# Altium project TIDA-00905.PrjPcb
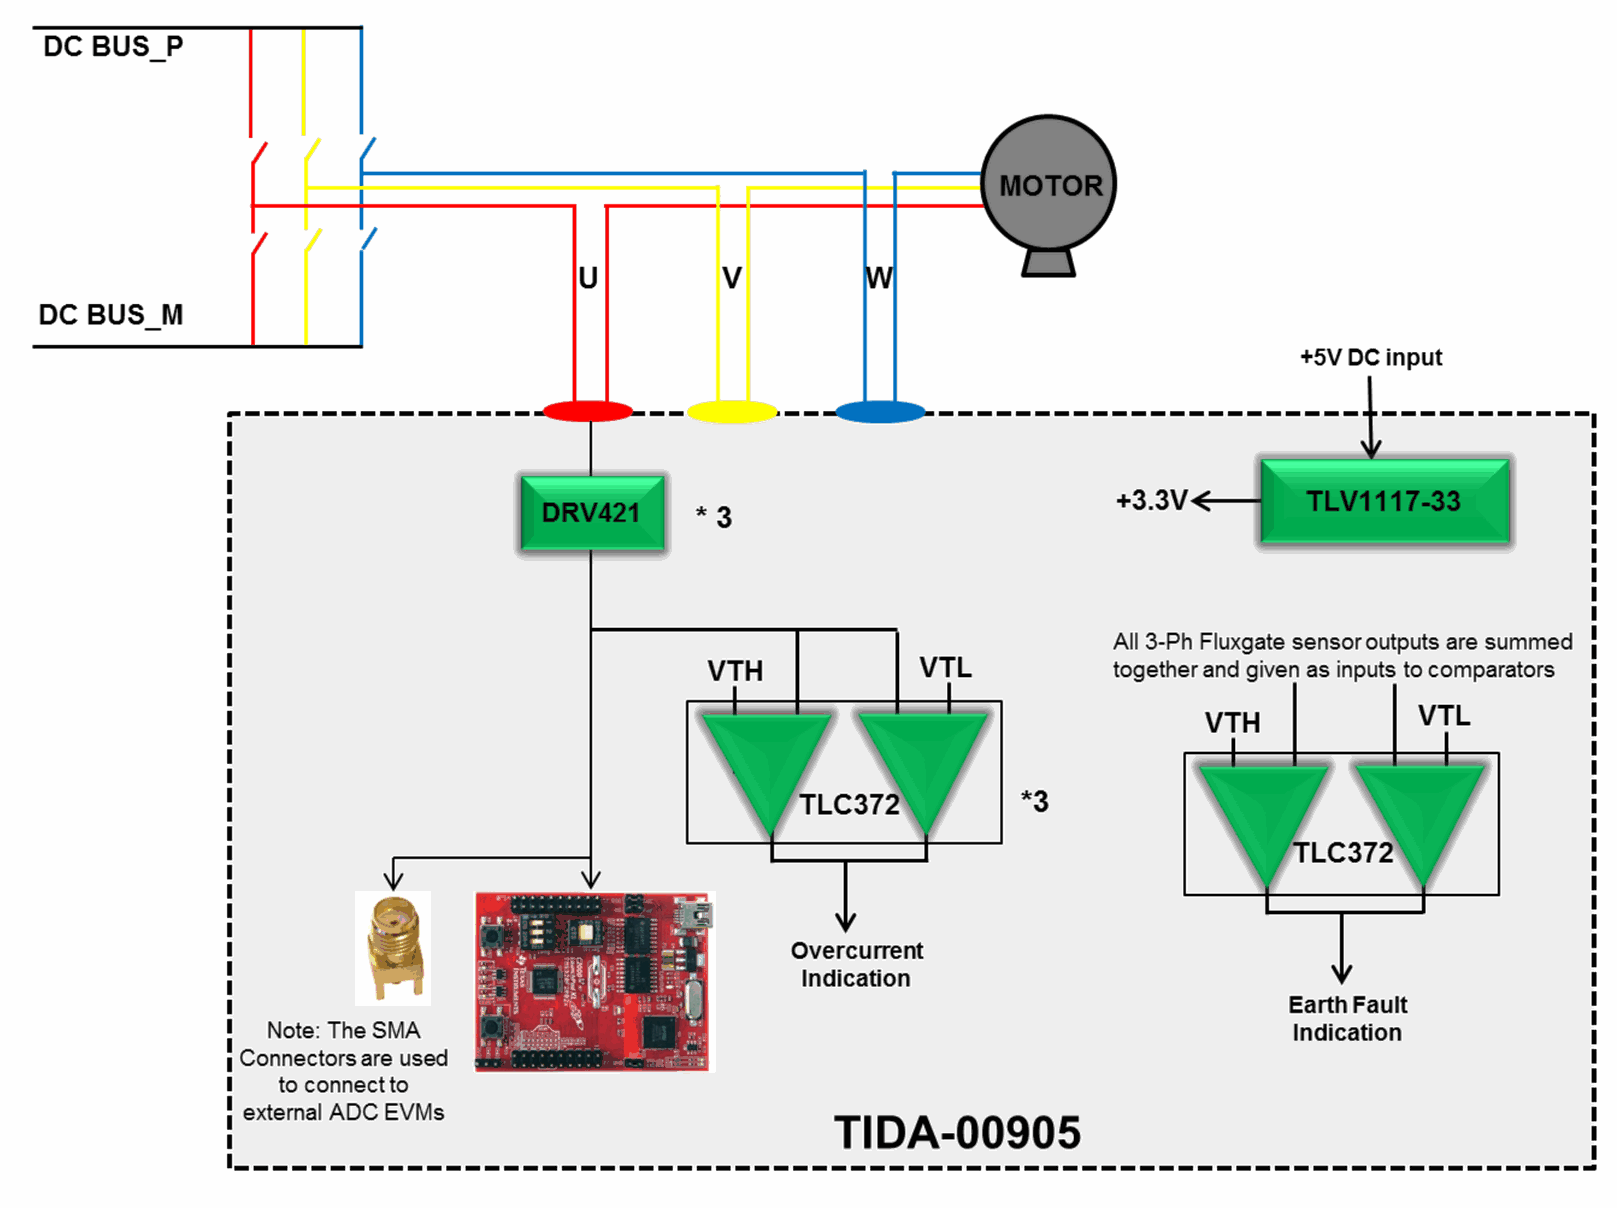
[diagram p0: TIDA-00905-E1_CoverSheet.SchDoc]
CopyrightYear: 2016; PCB_Layout: Avinash N; PCB_Rev: E1; PRJ_Customer: Public Release; PRJ_Engineer: Sanjay Pithadia; PRJ_Number: TIDA-00905; PRJ_Title: 3-Ph Current Sensing using DRV421; SCH_Rev: E1; TechSupport: http://www.ti.com/support; TID: TIDA-00905
6 sheets, 197 parts. Net scope: flat (ports and power ports of the same name join across sheets).
Board file: TIDA-00905-E1.PcbDoc
Sheets:
  TIDA-00905-E1_CoverSheet.SchDoc
  TIDA-00905-E1_P1.SchDoc
  TIDA-00905-E1_P2.SchDoc
  TIDA-00905-E1_P3.SchDoc
  TIDA-00905-E1_P4.SchDoc
  TIDA-00905-E1_Hardware.SchDoc

## Sheet TIDA-00905-E1_CoverSheet.SchDoc: Block Diagram
size 431 x 279 mm; Date: Not shown in title block; ApprovedBy: Not shown in title block; CheckedBy: Not shown in title block; Author: Not shown in title block; CompanyName: Not shown in title block; DrawnBy: Sanjay Pithadia; Engineer: Sanjay Pithadia; Organization: Not shown in title block; Address1: Not shown in title block; Address2: Not shown in title block; Address3: Not shown in title block; Address4: Not shown in title block; DocumentNumber: 1; Revision: Use project parameter SCH_Rev; SheetNumber: 1; SheetTotal: 6; PageSetup: Record=PageOptions¦CenterHorizontal=True¦CenterVertical=True¦PrintScale=1.00¦XCorrection=1.00¦YCorrection=1.00¦PrintKind=0¦BorderSize=5000000¦LeftOffset=0¦BottomOffset=0¦Orientation=2¦PaperLength=1000¦PaperWidth=1000¦Scale=100¦PaperSource=15¦PrintQuality=600¦MediaType=1¦DitherType=10¦PaperKind=Letter¦PrintScaleMode=1

## Sheet TIDA-00905-E1_P1.SchDoc
size 431 x 279 mm; Date: Not shown in title block; ApprovedBy: Not shown in title block; CheckedBy: Not shown in title block; Author: Not shown in title block; CompanyName: Not shown in title block; Engineer: Not shown in title block; Organization: Not shown in title block; Address1: Not shown in title block; Address2: Not shown in title block; Address3: Not shown in title block; Address4: Not shown in title block; DocumentNumber: 1; Revision: Use project parameter SCH_Rev; SheetNumber: 2; SheetTotal: 6; PageSetup: Record=PageOptions¦CenterHorizontal=True¦CenterVertical=True¦PrintScale=1.00¦XCorrection=1.00¦YCorrection=1.00¦PrintKind=0¦BorderSize=5000000¦LeftOffset=0¦BottomOffset=0¦Orientation=2¦PaperLength=1000¦PaperWidth=1000¦Scale=100¦PaperSource=15¦PrintQuality=600¦MediaType=1¦DitherType=10¦PaperKind=Letter¦PrintScaleMode=1
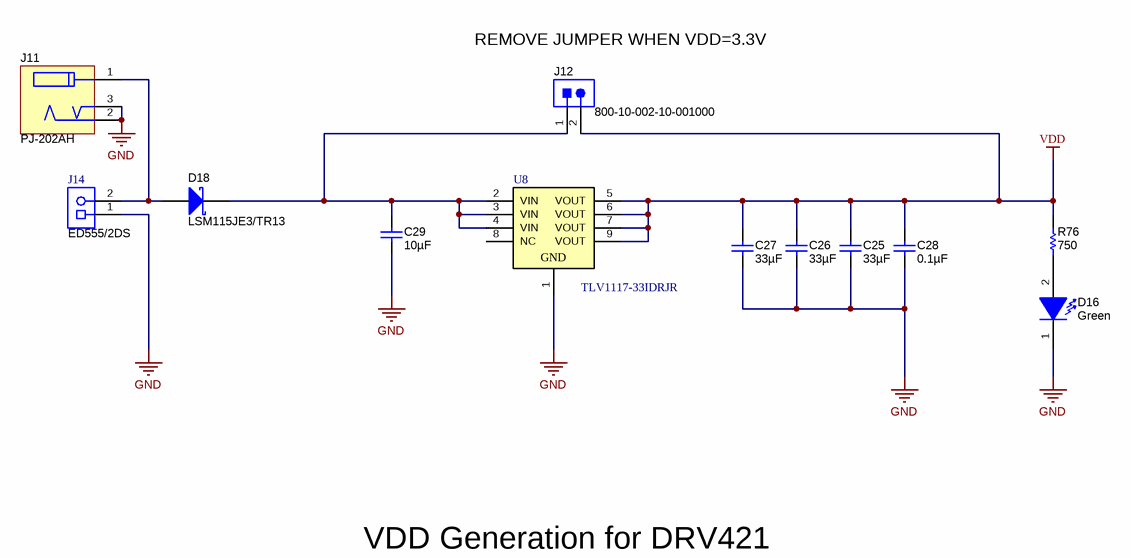
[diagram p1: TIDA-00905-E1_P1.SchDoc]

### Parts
C25  ValueDisplayed: 33µF  [0805_HV]  (hidden comment: C2012X5R1A336M125AC)
C26  ValueDisplayed: 33µF  [0805_HV]  (hidden comment: C2012X5R1A336M125AC)
C27  ValueDisplayed: 33µF  [0805_HV]  (hidden comment: C2012X5R1A336M125AC)
C28  ValueDisplayed: 0.1µF  [0603]  (hidden comment: GRM188R71C104KA01D)
C29  ValueDisplayed: 10µF  [0805_HV]  (hidden comment: GRM21BR61C106KE15L)
D16  value Green  [WL-SMCW_GREEN]  (hidden comment: 150060GS75000)
D18  LSM115JE3/TR13  [DO-214BA]
J11  PJ-202AH  [CONN_CUI-PJ-202AH]
J12  800-10-002-10-001000  [Mill-Max_800-10-002-10-001000]
J14  ED555/2DS  [TERM_BLK_ED555-2DS]
R76  ValueDisplayed: 750  [0603]  (hidden comment: CRCW0603750RJNEA)
U8  TLV1117-33IDRJR  [DRJ0008A]

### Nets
GND: C25.2 C26.2 C27.2 C28.1 C29.2 D16.1(K) J11.2 J11.3 J14.1 U8.1(GND)
VDD: C25.1 C26.1 C27.1 C28.2 J12.2 R76.2 U8.5(VOUT) U8.6(VOUT) U8.7(VOUT) U8.9(VOUT)
NetC29_1: C29.1 D18.1(K) J12.1 U8.2(VIN) U8.3(VIN) U8.4(VIN)
NetD16_2: D16.2(A) R76.1
NetD18_2: D18.2(A) J11.1 J14.2

Not connected (* = marked no-connect by the designer): U8 8(NC)

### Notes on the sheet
- REMOVE JUMPER WHEN VDD=3.3V
- VDD Generation for DRV421

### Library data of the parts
C25-C27 = C2012X5R1A336M125AC: CAP, CERM, 33 µF, 10 V, +/- 20%, X5R, 0805; Manufacturer: TDK; Polarized: N; CompType: Capacitor; Value: 33uF; U/M: EA; Cap_F: 0.000033; Tolerance_%: 20; Value1: Unknown; VDC_V: 10; Value2: 10V; TaMin_C: -55; TaMax_C: 85; Cap_Case: 0805; AEC Category: Q200
C28 = GRM188R71C104KA01D: CAP, CERM, 0.1 µF, 16 V, +/- 10%, X7R, 0603; Manufacturer: MuRata; Polarized: N; CompType: Capacitor; Value: 0.1uF; U/M: EA; Cap_F: 0.0000001; Tolerance_%: 10; Value1: Unknown; VDC_V: 16; Value2: 16V; TaMin_C: -55; TaMax_C: 125; AEC Category: Q200
C29 = GRM21BR61C106KE15L: CAP, CERM, 10uF, 16V, +/-10%, X5R, 0805; Manufacturer: MuRata; Polarized: N; CompType: Capacitor; U/M: EA; Cap_F: 0.00001; Tolerance_%: 10; ESR_Ohm: 0.008; Value1: 0.008 ohm; VDC_V: 16; TaMin_C: -55; TaMax_C: 85; Cap_Case: 0805
D16 = 150060GS75000: LED, Green, SMD; Manufacturer: Wurth Elektronik; Type: InGaN; Vf_V: 3.2; Value2: 3.2V; Io_A: 0.02; Tjmax_C: 85; Value1: W; Angle: 140; U/M: EA
D18 = LSM115JE3/TR13: Diode, Schottky, 15 V, 1 A, DO-214BA; Manufacturer: Microsemi; U/M: EA; Vf_V: 0.22; Value: 15V; Value1: 1A; Value2: 0.22V; Io_A: 1; Vr_V: 15; TJmax_C: 100; AEC Category: Q101
J11 = PJ-202AH: Connector, DC Jack 2.1X5.5 mm, TH; Manufacturer: CUI Inc.; SymbolCreator: a0799628; CompType: Power Jack
J12 = 800-10-002-10-001000: Header, 100mil, 2x1, TH; Manufacturer: Mill-Max; SymbolCreator: a0412235
J14 = ED555/2DS: Terminal Block, 3.5mm Pitch, 2x1, TH; Manufacturer: On-Shore Technology; SymbolCreator: a0412235; Pitch_mm: 3.5; Gender: Female; Shrouded: N; Row_Count: 1; ContactFinish: Brass; Current_A: 6; Voltage_V: 150; Cert_CULUS: Y
R76 = CRCW0603750RJNEA: RES, 750, 5%, 0.1 W, 0603; Manufacturer: Vishay-Dale; CompType: Resistor; Value: 750; Value_Code: 750R; Tolerance_%: 5; Power_W: 0.1; Value2: 0.1W; VDC_V: 75; TempCo: 200 ppm/C; EIA_Code: E24; U/M: EA; AEC Category: Q200
U8 = TLV1117-33IDRJR: LDO with 4.7 to 15 V Input and 3.3 V Output, -40 to 125 degC, 8-Pin SON (DRJ), Green (RoHS & no Sb/Br); Manufacturer: Texas Instruments; Alternate PartNumber: Equivalent; Iout(Max)(A): 0.8; Iq(Typ)(mA): 5; Vin(Max)(V): 15; Vin(Min)(V): 4.7; Vout(Max)(V): 3.3

## Sheet TIDA-00905-E1_P2.SchDoc
size 431 x 279 mm; Date: Not shown in title block; ApprovedBy: Not shown in title block; CheckedBy: Not shown in title block; Author: Not shown in title block; CompanyName: Not shown in title block; Engineer: Not shown in title block; Organization: Not shown in title block; Address1: Not shown in title block; Address2: Not shown in title block; Address3: Not shown in title block; Address4: Not shown in title block; DocumentNumber: 1; Revision: Use project parameter SCH_Rev; SheetNumber: 3; SheetTotal: 6; PageSetup: Record=PageOptions¦CenterHorizontal=True¦CenterVertical=True¦PrintScale=1.00¦XCorrection=1.00¦YCorrection=1.00¦PrintKind=0¦BorderSize=5000000¦LeftOffset=0¦BottomOffset=0¦Orientation=2¦PaperLength=1000¦PaperWidth=1000¦Scale=100¦PaperSource=15¦PrintQuality=600¦MediaType=1¦DitherType=10¦PaperKind=Letter¦PrintScaleMode=1
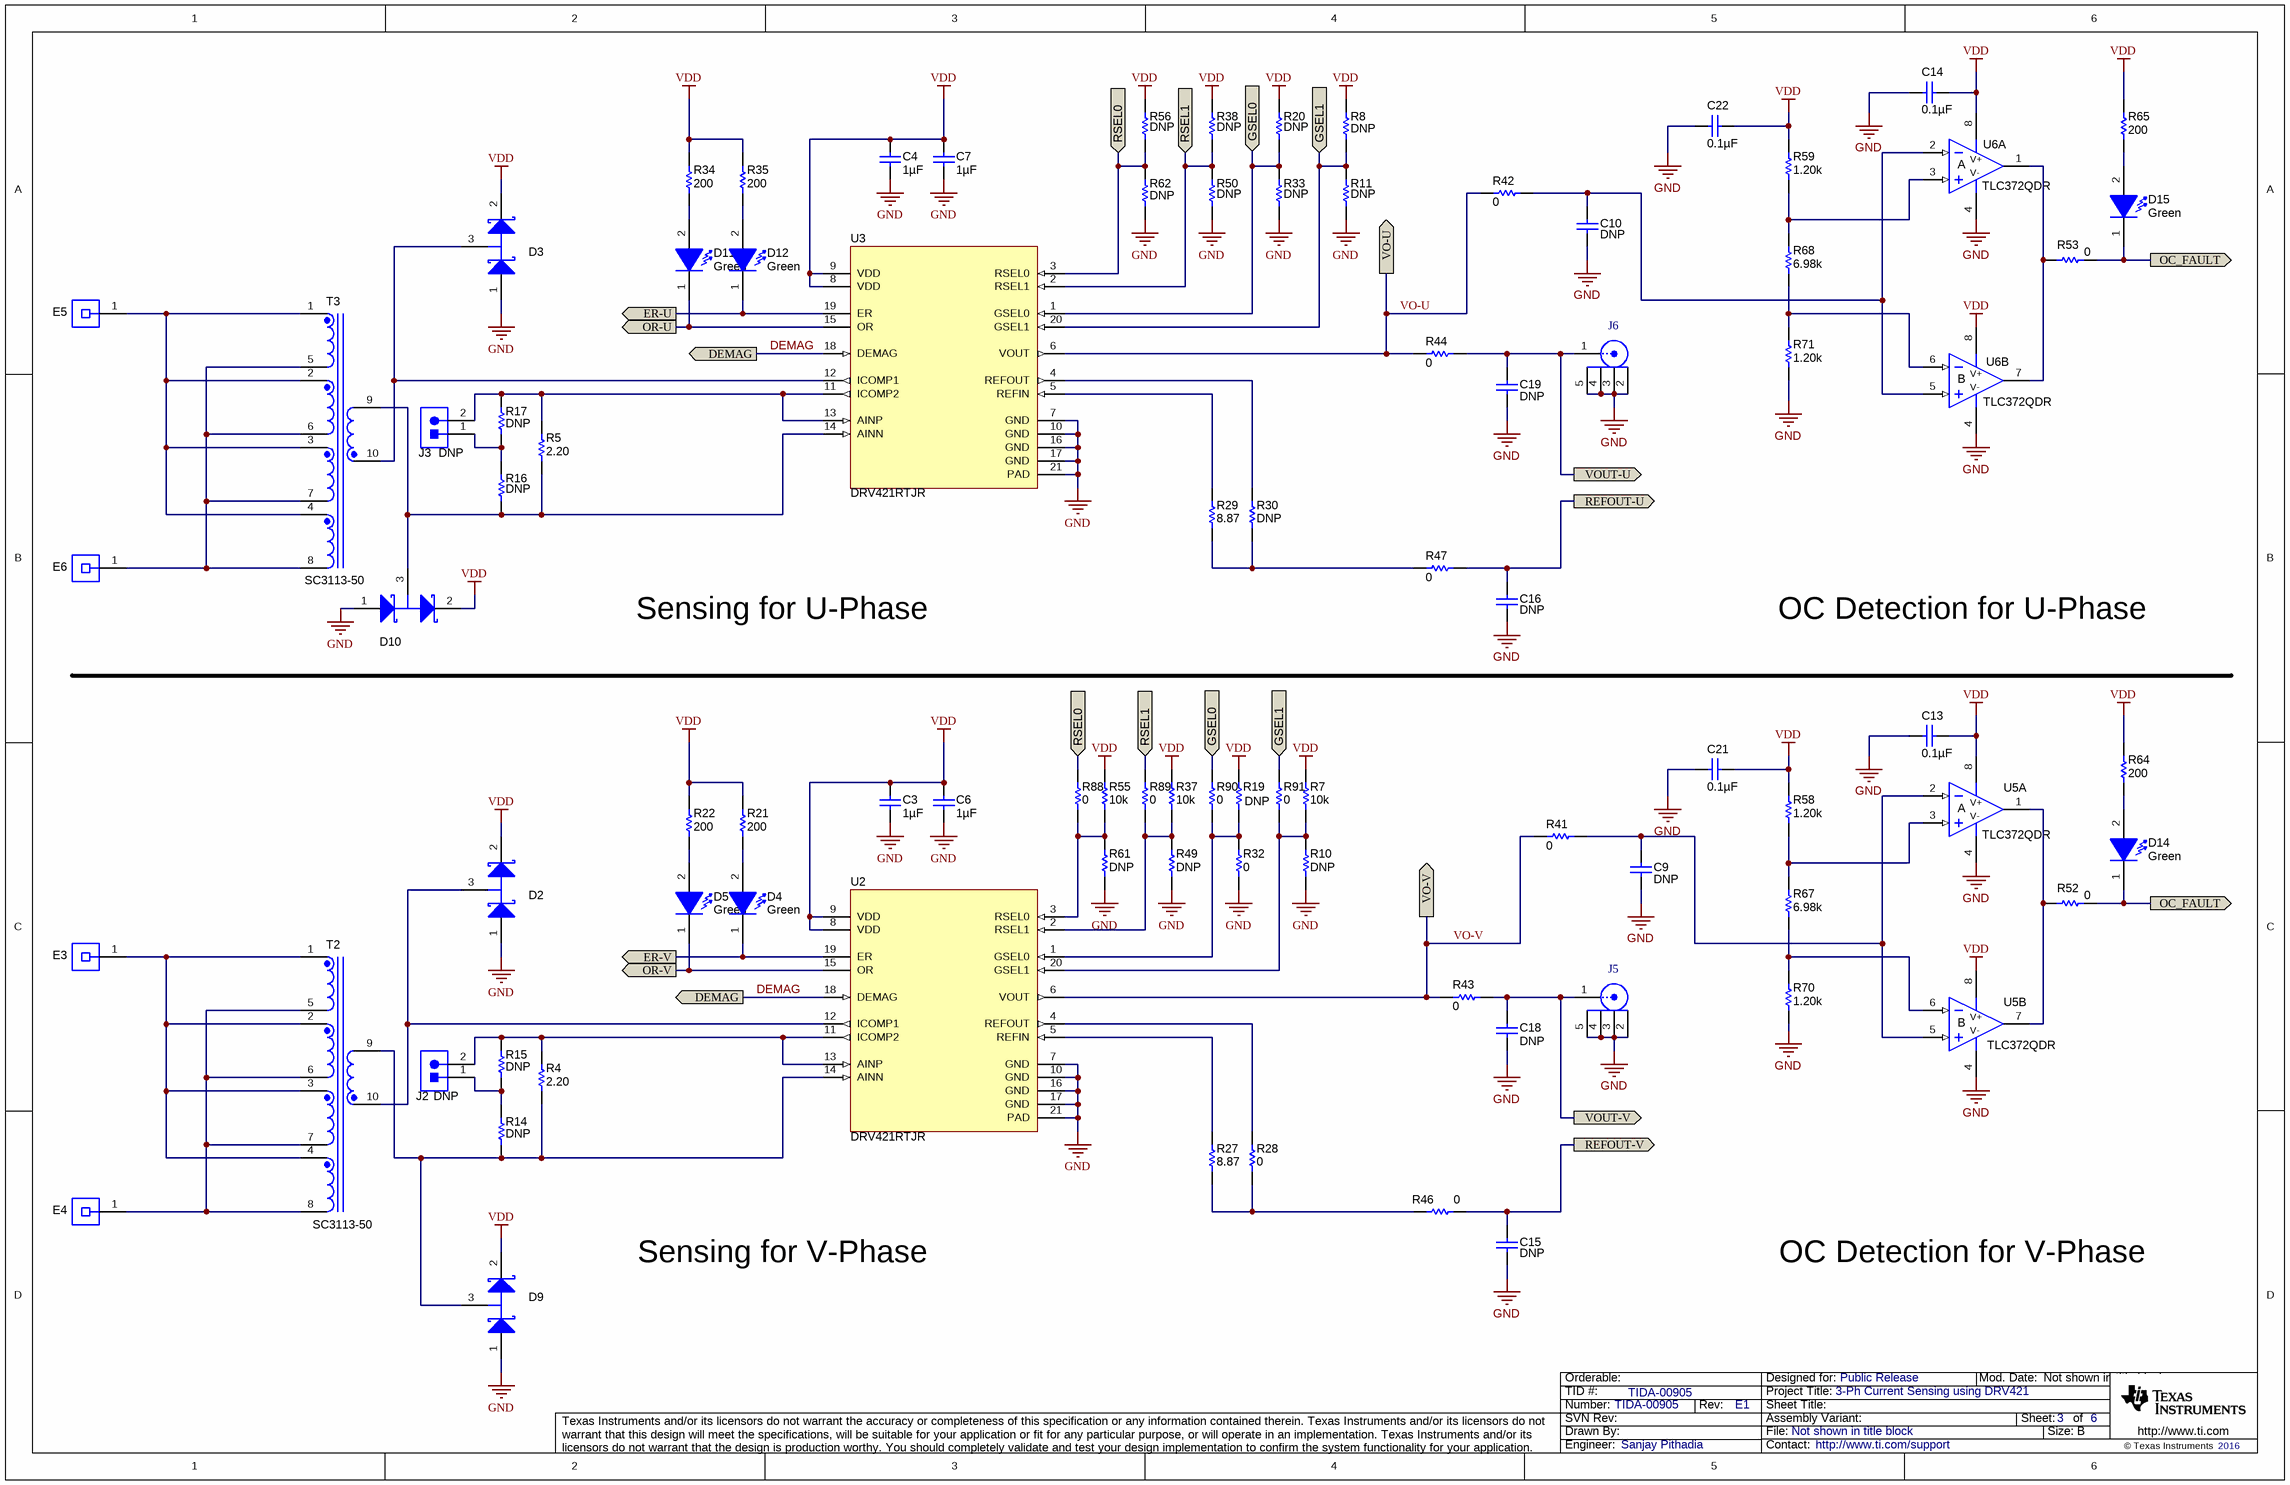
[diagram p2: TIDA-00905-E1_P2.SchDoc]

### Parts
C3  ValueDisplayed: 1µF  [0603_095]  (hidden comment: C0603C105K3RACTU)
C4  ValueDisplayed: 1µF  [0603_095]  (hidden comment: C0603C105K3RACTU)
C6  ValueDisplayed: 1µF  [0603_095]  (hidden comment: C0603C105K3RACTU)
C7  ValueDisplayed: 1µF  [0603_095]  (hidden comment: C0603C105K3RACTU)
C9  0603YC104JAT2A  [0603]  (value not drawn)
C10  0603YC104JAT2A  [0603]  (value not drawn)
C13  ValueDisplayed: 0.1µF  [0603]  (hidden comment: C0603C104J4RACTU)
C14  ValueDisplayed: 0.1µF  [0603]  (hidden comment: C0603C104J4RACTU)
C15  0603YC104JAT2A  [0603]  (value not drawn)
C16  0603YC104JAT2A  [0603]  (value not drawn)
C18  0603YC104JAT2A  [0603]  (value not drawn)
C19  0603YC104JAT2A  [0603]  (value not drawn)
C21  ValueDisplayed: 0.1µF  [0603]  (hidden comment: C0603C104J4RACTU)
C22  ValueDisplayed: 0.1µF  [0603]  (hidden comment: C0603C104J4RACTU)
D2  BAT54S-E3-08  [SOT-23]  (value not drawn)
D3  BAT54S-E3-08  [SOT-23]  (value not drawn)
D4  value Green  [WL-SMCW_GREEN]  (hidden comment: 150060GS75000)
D5  value Green  [WL-SMCW_GREEN]  (hidden comment: 150060GS75000)
D9  BAT54S-E3-08  [SOT-23]  (value not drawn)
D10  BAT54S-E3-08  [SOT-23]  (value not drawn)
D11  value Green  [WL-SMCW_GREEN]  (hidden comment: 150060GS75000)
D12  value Green  [WL-SMCW_GREEN]  (hidden comment: 150060GS75000)
D14  value Green  [WL-SMCW_GREEN]  (hidden comment: 150060GS75000)
D15  value Green  [WL-SMCW_GREEN]  (hidden comment: 150060GS75000)
E3  7461086  [Wurth_7461086]  (value not drawn)
E4  7461086  [Wurth_7461086]  (value not drawn)
E5  7461086  [Wurth_7461086]  (value not drawn)
E6  7461086  [Wurth_7461086]  (value not drawn)
J2  TMM-102-01-F-S  [Samtec_TMM-102-01-F-S]  (value not drawn)
J3  TMM-102-01-F-S  [Samtec_TMM-102-01-F-S]  (value not drawn)
J5  142-0701-201  [Johnson_142-0701-20x]  (value not drawn)
J6  142-0701-201  [Johnson_142-0701-20x]  (value not drawn)
R4  ValueDisplayed: 2.20  [1206]  (hidden comment: RC1206FR-072R2L)
R5  ValueDisplayed: 2.20  [1206]  (hidden comment: RC1206FR-072R2L)
R7  ValueDisplayed: 10k  [0603]  (hidden comment: RC0603JR-0710KL)
R8  RC0603JR-0710KL  [0603]  (value not drawn)
R10  ERJ-3GEY0R00V  [0603]  (value not drawn)
R11  ERJ-3GEY0R00V  [0603]  (value not drawn)
R14  CRCW12061R20FKEA  [1206]  (value not drawn)
R15  CSR1206FK1R00  [1206]  (value not drawn)
R16  CRCW12061R20FKEA  [1206]  (value not drawn)
R17  CSR1206FK1R00  [1206]  (value not drawn)
R19  RC0603JR-0710KL  [0603]  (value not drawn)
R20  RC0603JR-0710KL  [0603]  (value not drawn)
R21  ValueDisplayed: 200  [0603]  (hidden comment: CRCW0603200RJNEA)
R22  ValueDisplayed: 200  [0603]  (hidden comment: CRCW0603200RJNEA)
R27  ValueDisplayed: 8.87  [0603]  (hidden comment: CRCW06038R87FKEA)
R28  ValueDisplayed: 0  [0603]  (hidden comment: ERJ-3GEY0R00V)
R29  ValueDisplayed: 8.87  [0603]  (hidden comment: CRCW06038R87FKEA)
R30  ERJ-3GEY0R00V  [0603]  (value not drawn)
R32  ValueDisplayed: 0  [0603]  (hidden comment: ERJ-3GEY0R00V)
R33  ERJ-3GEY0R00V  [0603]  (value not drawn)
R34  ValueDisplayed: 200  [0603]  (hidden comment: CRCW0603200RJNEA)
R35  ValueDisplayed: 200  [0603]  (hidden comment: CRCW0603200RJNEA)
R37  ValueDisplayed: 10k  [0603]  (hidden comment: RC0603JR-0710KL)
R38  RC0603JR-0710KL  [0603]  (value not drawn)
R41  ValueDisplayed: 0  [0603]  (hidden comment: RC0603JR-070RL)
R42  ValueDisplayed: 0  [0603]  (hidden comment: RC0603JR-070RL)
R43  ValueDisplayed: 0  [0603]  (hidden comment: RC0603JR-070RL)
R44  ValueDisplayed: 0  [0603]  (hidden comment: RC0603JR-070RL)
R46  ValueDisplayed: 0  [0603]  (hidden comment: ERJ-3GEY0R00V)
R47  ValueDisplayed: 0  [0603]  (hidden comment: ERJ-3GEY0R00V)
R49  ERJ-3GEY0R00V  [0603]  (value not drawn)
R50  ERJ-3GEY0R00V  [0603]  (value not drawn)
R52  ValueDisplayed: 0  [0603]  (hidden comment: RC0603JR-070RL)
R53  ValueDisplayed: 0  [0603]  (hidden comment: RC0603JR-070RL)
R55  ValueDisplayed: 10k  [0603]  (hidden comment: RC0603JR-0710KL)
R56  RC0603JR-0710KL  [0603]  (value not drawn)
R58  ValueDisplayed: 1.20k  [0603]  (hidden comment: RG1608P-122-B-T5)
R59  ValueDisplayed: 1.20k  [0603]  (hidden comment: RG1608P-122-B-T5)
R61  ERJ-3GEY0R00V  [0603]  (value not drawn)
R62  ERJ-3GEY0R00V  [0603]  (value not drawn)
R64  ValueDisplayed: 200  [0603]  (hidden comment: CRCW0603200RJNEA)
R65  ValueDisplayed: 200  [0603]  (hidden comment: CRCW0603200RJNEA)
R67  ValueDisplayed: 6.98k  [0603]  (hidden comment: RT0603BRD076K98L)
R68  ValueDisplayed: 6.98k  [0603]  (hidden comment: RT0603BRD076K98L)
R70  ValueDisplayed: 1.20k  [0603]  (hidden comment: RG1608P-122-B-T5)
R71  ValueDisplayed: 1.20k  [0603]  (hidden comment: RG1608P-122-B-T5)
R88  ValueDisplayed: 0  [0603]  (hidden comment: RC0603JR-070RL)
R89  ValueDisplayed: 0  [0603]  (hidden comment: RC0603JR-070RL)
R90  ValueDisplayed: 0  [0603]  (hidden comment: RC0603JR-070RL)
R91  ValueDisplayed: 0  [0603]  (hidden comment: RC0603JR-070RL)
T2  SC3113-50  [Sumida_SC3113]
T3  SC3113-50  [Sumida_SC3113]
U2  DRV421RTJR  [RTJ0020G]
U3  DRV421RTJR  [RTJ0020G]
U5  TLC372QDR  [D0008A_N]  (parts A,B of 2)
U6  TLC372QDR  [D0008A_N]  (parts A,B of 2)

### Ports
DEMAG (out), ER-U (out), ER-V (out), GSEL0, GSEL1, OC_FAULT (out), OR-U (out), OR-V (out), REFOUT-U (out), REFOUT-V (out), RSEL0, RSEL1, VO-U (out), VO-V (out), VOUT-U (out), VOUT-V (out)

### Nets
GND: C3.2 C4.2 C6.2 C7.2 C9.2 C10.2 C13.2 C14.2 C15.2 C16.2 C18.2 C19.2 C21.2 C22.2 D2.1(A) D3.1(A) D9.1(A) D10.1(A) J5.2 J5.3 J5.4 J5.5 J6.2 J6.3 J6.4 J6.5 R10.2 R11.2 R32.2 R33.2 R49.2 R50.2 R61.2 R62.2 R70.1 R71.1 U2.7(GND) U2.10(GND) U2.16(GND) U2.17(GND) U2.21(PAD) U3.7(GND) U3.10(GND) U3.16(GND) U3.17(GND) U3.21(PAD) U5.4(V-) U6.4(V-)
VDD: C3.1 C4.1 C6.1 C7.1 C13.1 C14.1 C21.1 C22.1 D2.2(K) D3.2(K) D9.2(K) D10.2(K) R7.2 R8.2 R19.2 R20.2 R21.2 R22.2 R34.2 R35.2 R37.2 R38.2 R55.2 R56.2 R58.2 R59.2 R64.2 R65.2 U2.8(VDD) U2.9(VDD) U3.8(VDD) U3.9(VDD) U5.8(V+) U6.8(V+)
DEMAG: U2.18(DEMAG) U3.18(DEMAG) ; port DEMAG
ER-U: D12.1(K) U3.19(ER) ; port ER-U
ER-V: D4.1(K) U2.19(ER) ; port ER-V
GSEL0: R20.1 R33.1 R90.1 U3.1(GSEL0) ; port GSEL0
GSEL1: R8.1 R11.1 R91.1 U3.20(GSEL1) ; port GSEL1
OC_FAULT: D14.1(K) D15.1(K) R52.2 R53.2 ; port OC_FAULT
OR-U: D11.1(K) U3.15(OR) ; port OR-U
OR-V: D5.1(K) U2.15(OR) ; port OR-V
REFOUT-U: C16.1 R47.2 ; port REFOUT-U
REFOUT-V: C15.1 R46.2 ; port REFOUT-V
RSEL0: R56.1 R62.1 R88.1 U3.3(RSEL0) ; port RSEL0
RSEL1: R38.1 R50.1 R89.1 U3.2(RSEL1) ; port RSEL1
VO-U: R42.1 R44.1 U3.6(VOUT) ; port VO-U
VO-V: R41.1 R43.1 U2.6(VOUT) ; port VO-V
VOUT-U: C19.1 J6.1 R44.2 ; port VOUT-U
VOUT-V: C18.1 J5.1 R43.2 ; port VOUT-V
NetC9_1: C9.1 R41.2 U5.2(IN-) U5.5(IN+)
NetC10_1: C10.1 R42.2 U6.2(IN-) U6.5(IN+)
NetD2_3: D2.3(C) T2.10 U2.12(ICOMP1)
NetD3_3: D3.3(C) T3.10 U3.12(ICOMP1)
NetD4_2: D4.2(A) R21.1
NetD5_2: D5.2(A) R22.1
NetD9_3: D9.3(C) R4.1 R14.1 T2.9 U2.14(AINN)
NetD10_3: D10.3(C) R5.1 R16.1 T3.9 U3.14(AINN)
NetD11_2: D11.2(A) R34.1
NetD12_2: D12.2(A) R35.1
NetD14_2: D14.2(A) R64.1
NetD15_2: D15.2(A) R65.1
NetE3_1: E3.1 T2.1 T2.2 T2.3 T2.4
NetE4_1: E4.1 T2.5 T2.6 T2.7 T2.8
NetE5_1: E5.1 T3.1 T3.2 T3.3 T3.4
NetE6_1: E6.1 T3.5 T3.6 T3.7 T3.8
NetJ2_1: J2.1 R14.2 R15.1
NetJ2_2: J2.2 R4.2 R15.2 U2.11(ICOMP2) U2.13(AINP)
NetJ3_1: J3.1 R16.2 R17.1
NetJ3_2: J3.2 R5.2 R17.2 U3.11(ICOMP2) U3.13(AINP)
NetR7_1: R7.1 R10.1 R91.2 U2.20(GSEL1)
NetR19_1: R19.1 R32.1 R90.2 U2.1(GSEL0)
NetR27_1: R27.1 U2.5(REFIN)
NetR27_2: R27.2 R28.1 R46.1
NetR28_2: R28.2 U2.4(REFOUT)
NetR29_1: R29.1 U3.5(REFIN)
NetR29_2: R29.2 R30.1 R47.1
NetR30_2: R30.2 U3.4(REFOUT)
NetR37_1: R37.1 R49.1 R89.2 U2.2(RSEL1)
NetR52_1: R52.1 U5.1(OUT) U5.7(OUT)
NetR53_1: R53.1 U6.1(OUT) U6.7(OUT)
NetR55_1: R55.1 R61.1 R88.2 U2.3(RSEL0)
NetR58_1: R58.1 R67.2 U5.3(IN+)
NetR59_1: R59.1 R68.2 U6.3(IN+)
NetR67_1: R67.1 R70.2 U5.6(IN-)
NetR68_1: R68.1 R71.2 U6.6(IN-)

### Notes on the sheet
- Sensing for U-Phase
- OC Detection for U-Phase
- Sensing for V-Phase
- OC Detection for V-Phase

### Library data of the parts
C3 C4 C6 C7 = C0603C105K3RACTU: CAP, CERM, 1 µF, 25 V, +/- 10%, X7R, 0603_095; Manufacturer: Kemet; Polarized: N; CompType: Capacitor; Value: 1uF; U/M: EA; Cap_F: 0.000001; Tolerance_%: 10; Value1: Unknown; VDC_V: 25; Value2: 25V; TaMin_C: -55; TaMax_C: 125; Cap_Case: 0603
C9 C10 C15 C16 C18 C19 = 0603YC104JAT2A: CAP, CERM, 0.1 µF, 16 V, +/- 5%, X7R, 0603; Manufacturer: AVX; Polarized: N; CompType: Capacitor; Value: 0.1uF; ValueDisplayed: 0.1µF; U/M: EA; Cap_F: 0.0000001; Tolerance_%: 5; ESR_ohm: 0.039; Value1: 0.039 ohm; VDC_V: 16; Value2: 16V; TaMin_C: -55; TaMax_C: 125
C13 C14 C21 C22 = C0603C104J4RACTU: CAP, CERM, 0.1uF, 16V, +/-5%, X7R, 0603; Manufacturer: Kemet; Polarized: N; CompType: Capacitor; U/M: EA; Cap_F: 0.0000001; Tolerance_%: 5; Value1: Unknown; VDC_V: 16; TaMin_C: -55; TaMax_C: 125
D2 D3 D9 D10 = BAT54S-E3-08: Diode, Schottky, 30 V, 0.2 A, SOT-23; Manufacturer: Vishay-Semiconductor; U/M: EA; Vf_V: 0.7; Value: 30V; Value1: 0.2A; Value2: 0.7V; Io_A: 0.2; Vr_V: 30; TJmax_C: 125; RJC_CperW: 430
D4 D5 D11 D12 D14 D15 = 150060GS75000: as D16 on sheet TIDA-00905-E1_P1
E3-E6 = 7461086: Power Element Bush, M4, 12, TH; Manufacturer: Wurth Elektronik; SymbolCreator: a0799628; CompType: Screw Terminal; Pitch_mm: 2.54; Gender: Female
J2 J3 = TMM-102-01-F-S: Header, 2mm, 2x1, Gold, TH; Manufacturer: Samtec; SymbolCreator: a0412235; U/M: EA
J5 J6 = 142-0701-201: Connector, TH, SMA; Manufacturer: Emerson Network Power; SymbolCreator: X0208326; U/M: EA
R4 R5 = RC1206FR-072R2L: RES, 2.20, 1%, 0.25 W, 1206; Manufacturer: Yageo America; CompType: Resistor; Value: 2.20; Res_ohm: 2.2; Value_Code: 2R20; Tolerance_%: 1; Power_W: 0.25; Value2: 0.25W; VDC_V: 200; TempCo: 200 ppm/C; U/M: EA; AEC Category: Q200
R7 R8 R19 R20 R37 R38 R55 R56 = RC0603JR-0710KL: RES, 10 k, 5%, 0.1 W, 0603; Manufacturer: Yageo America; CompType: Resistor; Value: 10k; Res_ohm: 10000; Value_Code: 10k0; Tolerance_%: 5; Power_W: 0.1; Value2: 0.1W; VDC_V: 50; TempCo: 100 ppm/C; EIA_Code: E24; U/M: EA
R10 R11 R32 R33 R46 R47 R49 R50 R61 R62 = ERJ-3GEY0R00V: RES, 0, 5%, 0.1 W, 0603; Manufacturer: Panasonic; CompType: Resistor; Value: 0; Value_Code: 0000; Tolerance_%: 5; Power_W: 0.1; Value2: 0.1W; VDC_V: 50; TempCo: 600 ppm/C; EIA_Code: E24; U/M: EA
R14 R16 = CRCW12061R20FKEA: RES, 1.20, 1%, 0.25 W, AEC-Q200 Grade 0, 1206; Manufacturer: Vishay-Dale; CompType: Resistor; Value: 1.20; Res_ohm: 1.2; Value_Code: 1R20; Tolerance_%: 1; Power_W: 0.25; Value2: 0.25W; VDC_V: 200; TempCo: 100 ppm/C; U/M: EA; AEC Category: Q200; AEC Qualified: Y; AEC Grade: 0
R15 R17 = CSR1206FK1R00: RES, 1.00, 1%, 0.5 W, 1206; Manufacturer: Stackpole Electronics Inc; CompType: Resistor; Value: 1.00; Res_ohm: 1; Value_Code: 1R00; Power_W: 0.5; Value2: 0.5W; TempCo: 100 ppm/C; EIA_Code: E96; U/M: EA; AEC Category: Q200
R21 R22 R34 R35 R64 R65 = CRCW0603200RJNEA: RES, 200, 5%, 0.1 W, 0603; Manufacturer: Vishay-Dale; CompType: Resistor; Value: 200; Value_Code: 200R; Tolerance_%: 5; Power_W: 0.1; Value2: 0.1W; VDC_V: 75; TempCo: 200 ppm/C; EIA_Code: E24; U/M: EA
R27 R29 = CRCW06038R87FKEA: RES, 8.87, 1%, 0.1 W, 0603; Manufacturer: Vishay-Dale; CompType: Resistor; Value: 8.87; Value_Code: 8R87; Tolerance_%: 1; Power_W: 0.1; Value2: 0.1W; VDC_V: 75; TempCo: 100 ppm/C; EIA_Code: E96; U/M: EA; AEC Category: Q200
R28 R30 = ERJ-3GEY0R00V: RES, 0, 5%, 0.1 W, 0603; Manufacturer: Panasonic; CompType: Resistor; Value: 0; Value_Code: 0000; Tolerance_%: 5; Power_W: 0.1; Value2: 0.1W; VDC_V: 50; TempCo: 600 ppm/C; EIA_Code: E24; U/M: EA; AEC Category: Q200
R41-R44 R52 R53 R88-R91 = RC0603JR-070RL: RES, 0, 5%, 0.1 W, 0603; Manufacturer: Yageo America; CompType: Resistor; Value: 0; Value_Code: 0000; Tolerance_%: 5; Power_W: 0.1; Value2: 0.1W; VDC_V: 50; TempCo: 200 ppm/C; EIA_Code: E24; U/M: EA
R58 R59 R70 R71 = RG1608P-122-B-T5: RES, 1.20 k, 0.1%, 0.1 W, 0603; Manufacturer: Susumu Co Ltd; CompType: Resistor; Value: 1.20k; Res_ohm: 1200; Value_Code: 1k20; Tolerance_%: 0.1; Value2: 0.1W; VDC_V: 75; TempCo: 25 ppm/C; EIA_Code: E192; U/M: EA; AEC Category: Q200
R67 R68 = RT0603BRD076K98L: RES, 6.98 k, 0.1%, 0.1 W, 0603; Manufacturer: Yageo America; CompType: Resistor; Value: 6.98k; Res_ohm: 6980; Value_Code: 6k98; Tolerance_%: 0.1; Value2: 0.1W; VDC_V: 75; TempCo: 25 ppm/C; EIA_Code: E192; U/M: EA; AEC Category: Q200
T2 T3 = SC3113-50: Transformer, TH; Manufacturer: Sumida; SymbolCreator: Altium
U2 U3 = DRV421RTJR: 5-V, Closed-Loop, Current Sense Conditioner with Integrated Fluxgate Sensor, RTJ0020G; Alternate PartNumber: DRV421RTJT; Manufacturer: Texas Instruments; SymbolCreator: Altium; CompType: IC; U/M: EA
U5 U6 = TLC372QDR: LinCMOS Dual Differential Comparators, D0008A; Manufacturer: Texas Instruments; SymbolCreator: a0411947; CompType: IC; U/M: EA

## Sheet TIDA-00905-E1_P3.SchDoc
size 431 x 279 mm; Date: Not shown in title block; ApprovedBy: Not shown in title block; CheckedBy: Not shown in title block; Author: Not shown in title block; CompanyName: Not shown in title block; Engineer: Not shown in title block; Organization: Not shown in title block; Address1: Not shown in title block; Address2: Not shown in title block; Address3: Not shown in title block; Address4: Not shown in title block; DocumentNumber: 1; Revision: Use project parameter SCH_Rev; SheetNumber: 4; SheetTotal: 6; PageSetup: Record=PageOptions¦CenterHorizontal=True¦CenterVertical=True¦PrintScale=1.00¦XCorrection=1.00¦YCorrection=1.00¦PrintKind=0¦BorderSize=5000000¦LeftOffset=0¦BottomOffset=0¦Orientation=2¦PaperLength=1000¦PaperWidth=1000¦Scale=100¦PaperSource=15¦PrintQuality=600¦MediaType=1¦DitherType=10¦PaperKind=Letter¦PrintScaleMode=1
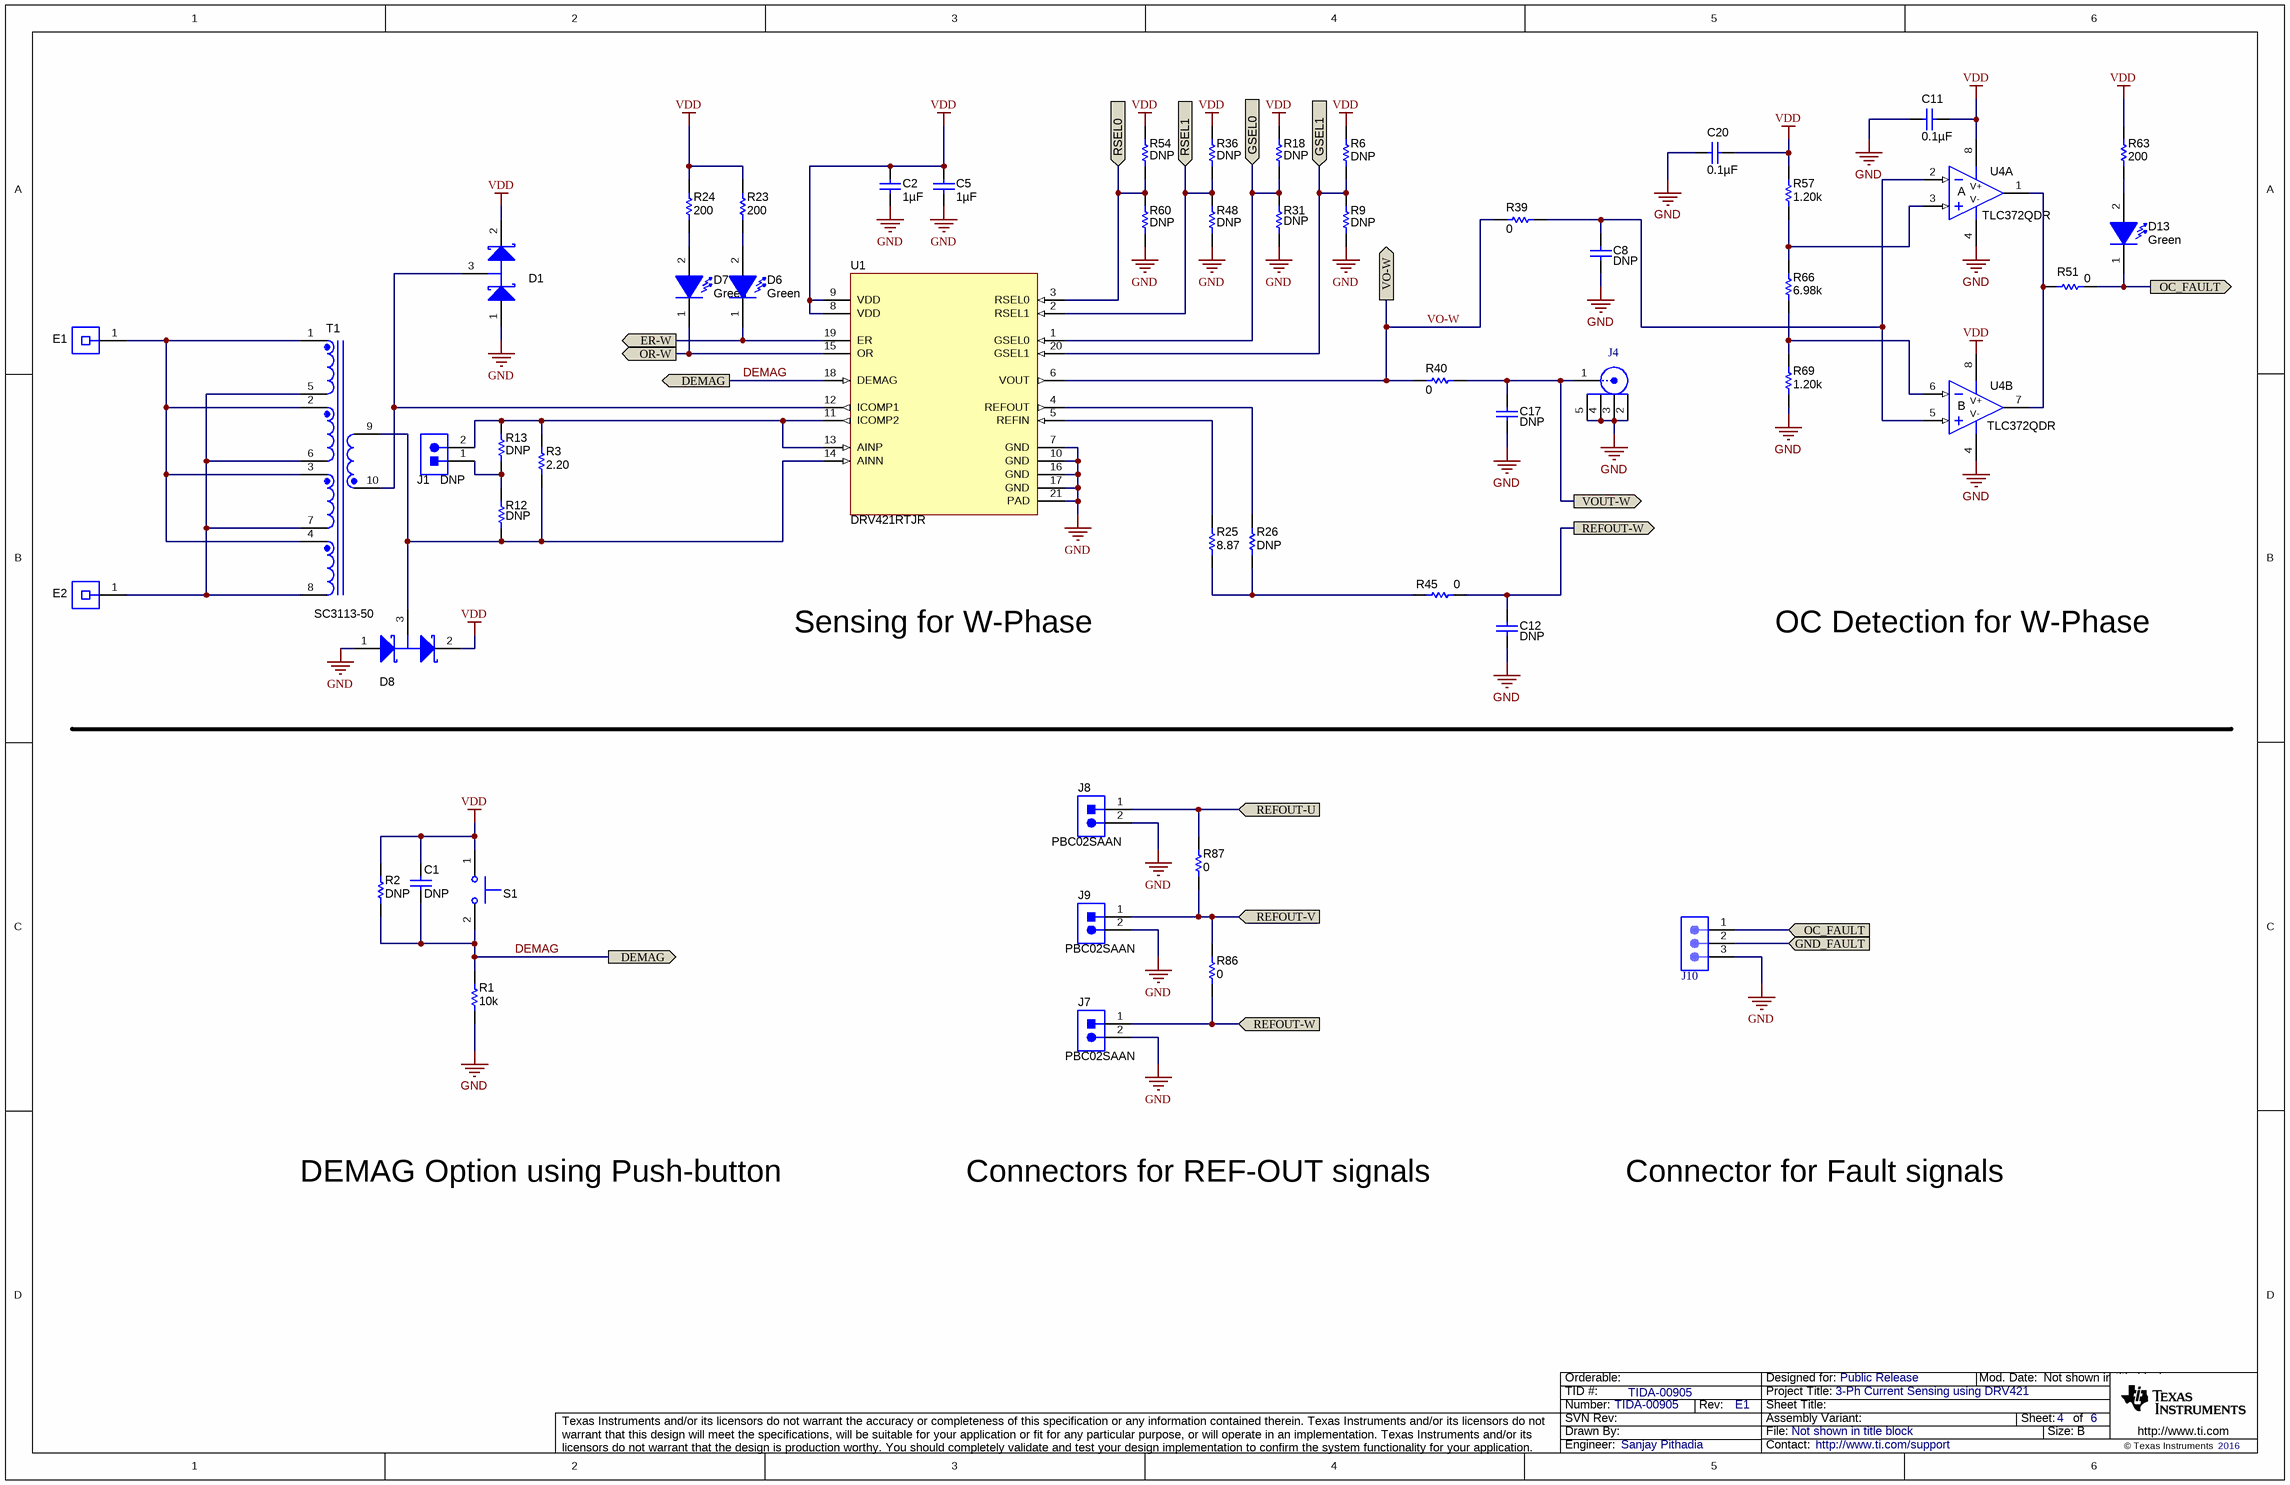
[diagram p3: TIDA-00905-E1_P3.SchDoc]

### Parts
C1  0603YC104JAT2A  [0603]  (value not drawn)
C2  ValueDisplayed: 1µF  [0603_095]  (hidden comment: C0603C105K3RACTU)
C5  ValueDisplayed: 1µF  [0603_095]  (hidden comment: C0603C105K3RACTU)
C8  0603YC104JAT2A  [0603]  (value not drawn)
C11  ValueDisplayed: 0.1µF  [0603]  (hidden comment: C0603C104J4RACTU)
C12  0603YC104JAT2A  [0603]  (value not drawn)
C17  0603YC104JAT2A  [0603]  (value not drawn)
C20  ValueDisplayed: 0.1µF  [0603]  (hidden comment: C0603C104J4RACTU)
D1  BAT54S-E3-08  [SOT-23]  (value not drawn)
D6  value Green  [WL-SMCW_GREEN]  (hidden comment: 150060GS75000)
D7  value Green  [WL-SMCW_GREEN]  (hidden comment: 150060GS75000)
D8  BAT54S-E3-08  [SOT-23]  (value not drawn)
D13  value Green  [WL-SMCW_GREEN]  (hidden comment: 150060GS75000)
E1  7461086  [Wurth_7461086]  (value not drawn)
E2  7461086  [Wurth_7461086]  (value not drawn)
J1  TMM-102-01-F-S  [Samtec_TMM-102-01-F-S]  (value not drawn)
J4  142-0701-201  [Johnson_142-0701-20x]  (value not drawn)
J7  PBC02SAAN  [Sullins_PBC02SAAN]
J8  PBC02SAAN  [Sullins_PBC02SAAN]
J9  PBC02SAAN  [Sullins_PBC02SAAN]
J10  PBC03SAAN  [PBC03SAAN]  (value not drawn)
R1  ValueDisplayed: 10k  [0603]  (hidden comment: RC0603JR-0710KL)
R2  RC0603JR-070RL  [0603]  (value not drawn)
R3  ValueDisplayed: 2.20  [1206]  (hidden comment: RC1206FR-072R2L)
R6  RC0603JR-0710KL  [0603]  (value not drawn)
R9  ERJ-3GEY0R00V  [0603]  (value not drawn)
R12  CRCW12061R20FKEA  [1206]  (value not drawn)
R13  CSR1206FK1R00  [1206]  (value not drawn)
R18  RC0603JR-0710KL  [0603]  (value not drawn)
R23  ValueDisplayed: 200  [0603]  (hidden comment: CRCW0603200RJNEA)
R24  ValueDisplayed: 200  [0603]  (hidden comment: CRCW0603200RJNEA)
R25  ValueDisplayed: 8.87  [0603]  (hidden comment: CRCW06038R87FKEA)
R26  ERJ-3GEY0R00V  [0603]  (value not drawn)
R31  ERJ-3GEY0R00V  [0603]  (value not drawn)
R36  RC0603JR-0710KL  [0603]  (value not drawn)
R39  ValueDisplayed: 0  [0603]  (hidden comment: RC0603JR-070RL)
R40  ValueDisplayed: 0  [0603]  (hidden comment: RC0603JR-070RL)
R45  ValueDisplayed: 0  [0603]  (hidden comment: ERJ-3GEY0R00V)
R48  ERJ-3GEY0R00V  [0603]  (value not drawn)
R51  ValueDisplayed: 0  [0603]  (hidden comment: RC0603JR-070RL)
R54  RC0603JR-0710KL  [0603]  (value not drawn)
R57  ValueDisplayed: 1.20k  [0603]  (hidden comment: RG1608P-122-B-T5)
R60  ERJ-3GEY0R00V  [0603]  (value not drawn)
R63  ValueDisplayed: 200  [0603]  (hidden comment: CRCW0603200RJNEA)
R66  ValueDisplayed: 6.98k  [0603]  (hidden comment: RT0603BRD076K98L)
R69  ValueDisplayed: 1.20k  [0603]  (hidden comment: RG1608P-122-B-T5)
R86  ValueDisplayed: 0  [0603]  (hidden comment: RC0603JR-070RL)
R87  ValueDisplayed: 0  [0603]  (hidden comment: RC0603JR-070RL)
S1  B3U-1000P  [SW_B3U-1000P]  (value not drawn)
T1  SC3113-50  [Sumida_SC3113]
U1  DRV421RTJR  [RTJ0020G]
U4  TLC372QDR  [D0008A_N]  (parts A,B of 2)

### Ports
DEMAG (out), ER-W (out), GND_FAULT (in), GSEL0, GSEL1, OC_FAULT (in), OC_FAULT (out), OR-W (out), REFOUT-U (in), REFOUT-V (in), REFOUT-W (in), REFOUT-W (out), RSEL0, RSEL1, VO-W (out), VOUT-W (out)

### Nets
GND: C2.2 C5.2 C8.2 C11.2 C12.2 C17.2 C20.2 D1.1(A) D8.1(A) J4.2 J4.3 J4.4 J4.5 J7.2 J8.2 J9.2 J10.3 R1.1 R9.2 R31.2 R48.2 R60.2 R69.1 U1.7(GND) U1.10(GND) U1.16(GND) U1.17(GND) U1.21(PAD) U4.4(V-)
VDD: C1.1 C2.1 C5.1 C11.1 C20.1 D1.2(K) D8.2(K) R2.2 R6.2 R18.2 R23.2 R24.2 R36.2 R54.2 R57.2 R63.2 S1.1 U1.8(VDD) U1.9(VDD) U4.8(V+)
DEMAG: C1.2 R1.2 R2.1 S1.2 U1.18(DEMAG) ; port DEMAG
ER-W: D6.1(K) U1.19(ER) ; port ER-W
GND_FAULT: J10.2 ; port GND_FAULT
GSEL0: R18.1 R31.1 U1.1(GSEL0) ; port GSEL0
GSEL1: R6.1 R9.1 U1.20(GSEL1) ; port GSEL1
OC_FAULT: D13.1(K) J10.1 R51.2 ; port OC_FAULT
OR-W: D7.1(K) U1.15(OR) ; port OR-W
REFOUT-U: J8.1 R87.1 ; port REFOUT-U
REFOUT-V: J9.1 R86.1 R87.2 ; port REFOUT-V
REFOUT-W: C12.1 J7.1 R45.2 R86.2 ; port REFOUT-W
RSEL0: R54.1 R60.1 U1.3(RSEL0) ; port RSEL0
RSEL1: R36.1 R48.1 U1.2(RSEL1) ; port RSEL1
VO-W: R39.1 R40.1 U1.6(VOUT) ; port VO-W
VOUT-W: C17.1 J4.1 R40.2 ; port VOUT-W
NetC8_1: C8.1 R39.2 U4.2(IN-) U4.5(IN+)
NetD1_3: D1.3(C) T1.10 U1.12(ICOMP1)
NetD6_2: D6.2(A) R23.1
NetD7_2: D7.2(A) R24.1
NetD8_3: D8.3(C) R3.1 R12.1 T1.9 U1.14(AINN)
NetD13_2: D13.2(A) R63.1
NetE1_1: E1.1 T1.1 T1.2 T1.3 T1.4
NetE2_1: E2.1 T1.5 T1.6 T1.7 T1.8
NetJ1_1: J1.1 R12.2 R13.1
NetJ1_2: J1.2 R3.2 R13.2 U1.11(ICOMP2) U1.13(AINP)
NetR25_1: R25.1 U1.5(REFIN)
NetR25_2: R25.2 R26.1 R45.1
NetR26_2: R26.2 U1.4(REFOUT)
NetR51_1: R51.1 U4.1(OUT) U4.7(OUT)
NetR57_1: R57.1 R66.2 U4.3(IN+)
NetR66_1: R66.1 R69.2 U4.6(IN-)

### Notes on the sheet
- Sensing for W-Phase
- OC Detection for W-Phase
- DEMAG Option using Push-button
- Connectors for REF-OUT signals
- Connector for Fault signals

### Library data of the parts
C1 = 0603YC104JAT2A: CAP, CERM, 0.1 µF, 16 V, +/- 5%, X7R, 0603; Manufacturer: AVX; Polarized: N; CompType: Capacitor; Value: 0.1uF; ValueDisplayed: 0.1µF; U/M: EA; Cap_F: 0.0000001; Tolerance_%: 5; ESR_ohm: 0.039; Value1: 0.039 ohm; VDC_V: 16; Value2: 16V; TaMin_C: -55; TaMax_C: 125; AEC Category: Q200
C2 C5 = C0603C105K3RACTU: as C3 on sheet TIDA-00905-E1_P2
C8 C12 C17 = 0603YC104JAT2A: as C9 on sheet TIDA-00905-E1_P2
C11 C20 = C0603C104J4RACTU: as C13 on sheet TIDA-00905-E1_P2
D1 D8 = BAT54S-E3-08: as D2 on sheet TIDA-00905-E1_P2
D6 D7 D13 = 150060GS75000: as D16 on sheet TIDA-00905-E1_P1
E1 E2 = 7461086: as E3 on sheet TIDA-00905-E1_P2
J1 = TMM-102-01-F-S: as J2 on sheet TIDA-00905-E1_P2
J4 = 142-0701-201: as J5 on sheet TIDA-00905-E1_P2
J7-J9 = PBC02SAAN: Header, 100mil, 2x1, Gold, TH; Manufacturer: Sullins Connector Solutions; SymbolCreator: a0412235; Pitch_mm: 2.54; Gender: Male; Shrouded: N; Row_Count: 1; Current_A: 3; Voltage_V: 1800; Cert_UL: Y
J10 = PBC03SAAN: Header, 100mil, 3x1, Gold, TH; Manufacturer: Sullins Connector Solutions
R1 R6 R18 R36 R54 = RC0603JR-0710KL: as R7 on sheet TIDA-00905-E1_P2
R2 R39 R40 R51 R86 R87 = RC0603JR-070RL: as R41 on sheet TIDA-00905-E1_P2
R3 = RC1206FR-072R2L: as R4 on sheet TIDA-00905-E1_P2
R9 R31 R45 R48 R60 = ERJ-3GEY0R00V: as R10 on sheet TIDA-00905-E1_P2
R12 = CRCW12061R20FKEA: as R14 on sheet TIDA-00905-E1_P2
R13 = CSR1206FK1R00: as R15 on sheet TIDA-00905-E1_P2
R23 R24 R63 = CRCW0603200RJNEA: as R21 on sheet TIDA-00905-E1_P2
R25 = CRCW06038R87FKEA: as R27 on sheet TIDA-00905-E1_P2
R26 = ERJ-3GEY0R00V: as R28 on sheet TIDA-00905-E1_P2
R57 R69 = RG1608P-122-B-T5: as R58 on sheet TIDA-00905-E1_P2
R66 = RT0603BRD076K98L: as R67 on sheet TIDA-00905-E1_P2
S1 = B3U-1000P: SWITCH TACTILE SPST-NO 0.05A 12V; Manufacturer: Omron Electronic Components; SymbolCreator: a0412235; VDC_V: 12; SwitchFunction: Off-Mom; PositionCount: 1; CurrentRating_mA: 50
T1 = SC3113-50: as T2 on sheet TIDA-00905-E1_P2
U1 = DRV421RTJR: as U2 on sheet TIDA-00905-E1_P2
U4 = TLC372QDR: as U5 on sheet TIDA-00905-E1_P2

## Sheet TIDA-00905-E1_P4.SchDoc
size 431 x 279 mm; Date: Not shown in title block; ApprovedBy: Not shown in title block; CheckedBy: Not shown in title block; Author: Not shown in title block; CompanyName: Not shown in title block; Engineer: Not shown in title block; Organization: Not shown in title block; Address1: Not shown in title block; Address2: Not shown in title block; Address3: Not shown in title block; Address4: Not shown in title block; DocumentNumber: 1; Revision: Use project parameter SCH_Rev; SheetNumber: 5; SheetTotal: 6; PageSetup: Record=PageOptions¦CenterHorizontal=True¦CenterVertical=True¦PrintScale=1.00¦XCorrection=1.00¦YCorrection=1.00¦PrintKind=0¦BorderSize=5000000¦LeftOffset=0¦BottomOffset=0¦Orientation=2¦PaperLength=1000¦PaperWidth=1000¦Scale=100¦PaperSource=15¦PrintQuality=600¦MediaType=1¦DitherType=10¦PaperKind=Letter¦PrintScaleMode=1
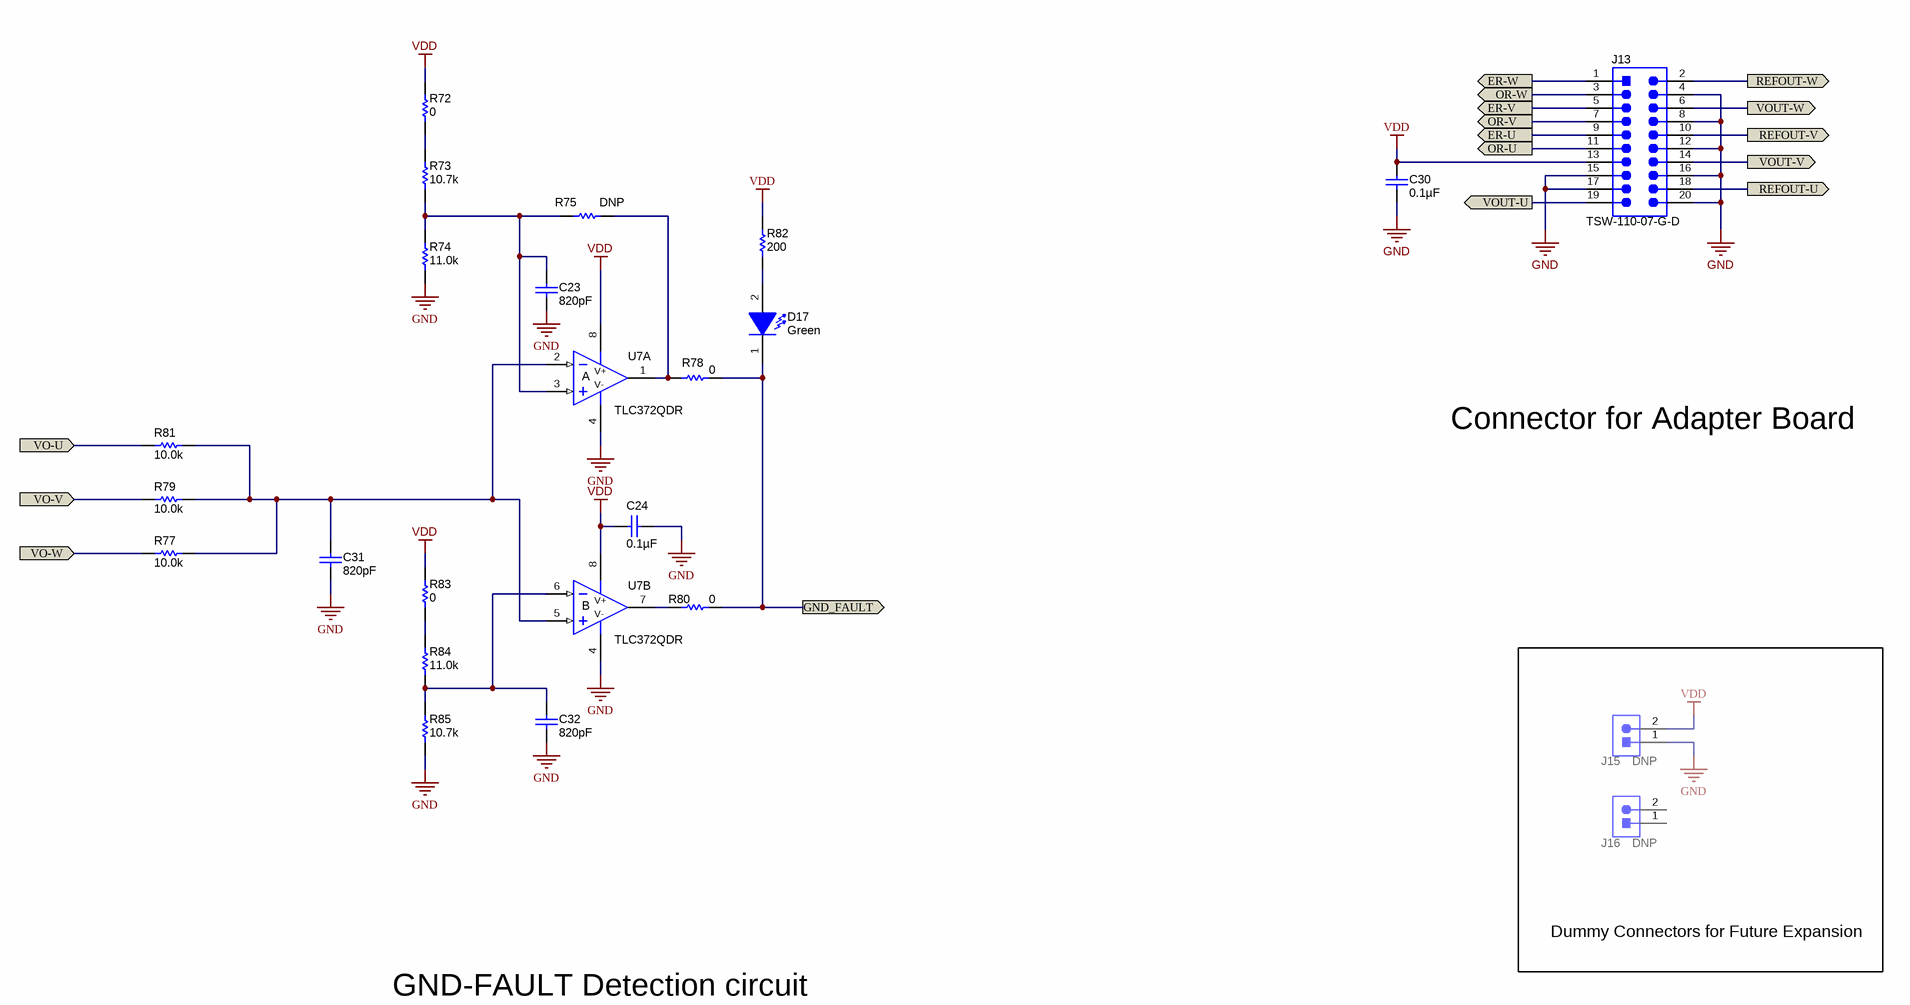
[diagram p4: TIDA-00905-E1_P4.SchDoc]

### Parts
C23  ValueDisplayed: 820pF  [0603]  (hidden comment: GRM188R71H821KA01D)
C24  ValueDisplayed: 0.1µF  [0603]  (hidden comment: GRM188R71H104KA93D)
C30  ValueDisplayed: 0.1µF  [0603]  (hidden comment: 0603YC104JAT2A)
C31  ValueDisplayed: 820pF  [0603]  (hidden comment: GRM188R71H821KA01D)
C32  ValueDisplayed: 820pF  [0603]  (hidden comment: GRM188R71H821KA01D)
D17  value Green  [WL-SMCW_GREEN]  (hidden comment: 150060GS75000)
J13  TSW-110-07-G-D  [TSW-110-07-G-D]
J15  TMM-102-01-F-S  [Samtec_TMM-102-01-F-S]  (value not drawn)
J16  TMM-102-01-F-S  [Samtec_TMM-102-01-F-S]  (value not drawn)
R72  ValueDisplayed: 0  [0603]  (hidden comment: ERJ-3GEY0R00V)
R73  ValueDisplayed: 10.7k  [0603]  (hidden comment: RG1608P-1072-B-T5)
R74  ValueDisplayed: 11.0k  [0603]  (hidden comment: RT0603BRD0711KL)
R75  CRCW06035M11FKEA  [0603]  (value not drawn)
R77  ValueDisplayed: 10.0k  [0603]  (hidden comment: PHT0603Y1002BGT200)
R78  ValueDisplayed: 0  [0603]  (hidden comment: RC0603JR-070RL)
R79  ValueDisplayed: 10.0k  [0603]  (hidden comment: PHT0603Y1002BGT200)
R80  ValueDisplayed: 0  [0603]  (hidden comment: RC0603JR-070RL)
R81  ValueDisplayed: 10.0k  [0603]  (hidden comment: PHT0603Y1002BGT200)
R82  ValueDisplayed: 200  [0603]  (hidden comment: CRCW0603200RJNEA)
R83  ValueDisplayed: 0  [0603]  (hidden comment: ERJ-3GEY0R00V)
R84  ValueDisplayed: 11.0k  [0603]  (hidden comment: RT0603BRD0711KL)
R85  ValueDisplayed: 10.7k  [0603]  (hidden comment: RG1608P-1072-B-T5)
U7  TLC372QDR  [D0008A_N]  (parts A,B of 2)

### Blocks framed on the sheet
Dummy Connectors for Future Expansion: J15 J16

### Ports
ER-U (out), ER-V (out), ER-W (out), GND_FAULT (out), OR-U (out), OR-V (out), OR-W (out), REFOUT-U (out), REFOUT-V (out), REFOUT-W (out), VO-U (in), VO-V (in), VO-W (in), VOUT-U (out), VOUT-V (out), VOUT-W (out)

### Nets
GND: C23.1 C24.1 C30.2 C31.1 C32.1 J13.4 J13.8 J13.12 J13.15 J13.16 J13.17 J13.20 J15.1 R74.2 R85.2 U7.4(V-)
VDD: C24.2 C30.1 J13.13 J15.2 R72.1 R82.2 R83.1 U7.8(V+)
ER-U: J13.9 ; port ER-U
ER-V: J13.5 ; port ER-V
ER-W: J13.1 ; port ER-W
GND_FAULT: D17.1(K) R78.2 R80.2 ; port GND_FAULT
OR-U: J13.11 ; port OR-U
OR-V: J13.7 ; port OR-V
OR-W: J13.3 ; port OR-W
REFOUT-U: J13.18 ; port REFOUT-U
REFOUT-V: J13.10 ; port REFOUT-V
REFOUT-W: J13.2 ; port REFOUT-W
VO-U: R81.1 ; port VO-U
VO-V: R79.1 ; port VO-V
VO-W: R77.1 ; port VO-W
VOUT-U: J13.19 ; port VOUT-U
VOUT-V: J13.14 ; port VOUT-V
VOUT-W: J13.6 ; port VOUT-W
NetC23_2: C23.2 R73.2 R74.1 R75.1 U7.3(IN+)
NetC31_2: C31.2 R77.2 R79.2 R81.2 U7.2(IN-) U7.5(IN+)
NetC32_2: C32.2 R84.2 R85.1 U7.6(IN-)
NetD17_2: D17.2(A) R82.1
NetR72_2: R72.2 R73.1
NetR75_2: R75.2 R78.1 U7.1(OUT)
NetR80_1: R80.1 U7.7(OUT)
NetR83_2: R83.2 R84.1

Not connected (* = marked no-connect by the designer): J16 1 2

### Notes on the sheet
- Connector for Adapter Board
- GND-FAULT Detection circuit

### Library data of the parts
C23 C31 C32 = GRM188R71H821KA01D: CAP, CERM, 820 pF, 50 V, +/- 10%, X7R, 0603; Manufacturer: MuRata; Polarized: N; CompType: Capacitor; Value: 820pF; U/M: EA; Cap_F: 0.00000000082; Tolerance_%: 10; Value1: Unknown; VDC_V: 50; Value2: 50V; TaMin_C: -55; TaMax_C: 125
C24 = GRM188R71H104KA93D: CAP, CERM, 0.1 µF, 50 V, +/- 10%, X7R, 0603; Manufacturer: MuRata; Polarized: N; CompType: Capacitor; Value: 0.1uF; U/M: EA; Cap_F: 0.0000001; Tolerance_%: 10; Value1: Unknown; VDC_V: 50; Value2: 50V; TaMin_C: -55; TaMax_C: 125
C30 = 0603YC104JAT2A: CAP, CERM, 0.1 µF, 16 V, +/- 5%, X7R, 0603; Manufacturer: AVX; Polarized: N; CompType: Capacitor; Value: 0.1uF; U/M: EA; Cap_F: 0.0000001; Tolerance_%: 5; ESR_ohm: 0.039; Value1: 0.039 ohm; VDC_V: 16; Value2: 16V; TaMin_C: -55; TaMax_C: 125
D17 = 150060GS75000: as D16 on sheet TIDA-00905-E1_P1
J13 = TSW-110-07-G-D: Header, 100mil, 10x2, Gold, TH; Manufacturer: Samtec; SymbolCreator: a0412235; Pitch_mm: 2.54; Gender: Male; Shrouded: N; Row_Count: 2; Current_A: 6.3; Voltage_V: 550; Cert_CSA: Y
J15 J16 = TMM-102-01-F-S: as J2 on sheet TIDA-00905-E1_P2
R72 R83 = ERJ-3GEY0R00V: as R10 on sheet TIDA-00905-E1_P2
R73 = RG1608P-1072-B-T5: RES, 10.7 k, 0.1%, 0.1 W, 0603; Manufacturer: Susumu Co Ltd; CompType: Resistor; Value: 10.7k; Res_ohm: 10700; Value_Code: 10k7; Tolerance_%: 0.1; Value2: 0.1W; VDC_V: 75; TempCo: 25 ppm/C; EIA_Code: E192; U/M: EA; AEC Category: Q200
R74 = RT0603BRD0711KL: RES, 11.0 k, 0.1%, 0.1 W, 0603; Manufacturer: Yageo America; CompType: Resistor; Value: 11.0k; Res_ohm: 11000; Value_Code: 11k0; Tolerance_%: 0.1; Value2: 0.1W; VDC_V: 75; TempCo: 25 ppm/C; EIA_Code: E192; U/M: EA; AEC Category: Q200
R75 = CRCW06035M11FKEA: RES, 5.11 M, 1%, 0.1 W, 0603; Manufacturer: Vishay-Dale; CompType: Resistor; Value: 5.11Meg; ValueDisplayed: 5.11M; Res_ohm: 5110000; Value_Code: 5M11; Tolerance_%: 1; Power_W: 0.1; Value2: 0.1W; VDC_V: 75; TempCo: 100 ppm/C; EIA_Code: E96; U/M: EA
R77 R79 R81 = PHT0603Y1002BGT200: RES, 10.0 k, 0.1%, 0.0375 W, 0603; Manufacturer: Vishay Sfernice; CompType: Resistor; Value: 10.0k; Res_ohm: 10000; Value_Code: 10k0; Tolerance_%: 0.1; Power_W: 0.0375; VDC_V: 75; TempCo: 15 ppm/C; EIA_Code: E192; U/M: EA; AEC Category: Q200
R78 R80 = RC0603JR-070RL: as R41 on sheet TIDA-00905-E1_P2
R82 = CRCW0603200RJNEA: as R21 on sheet TIDA-00905-E1_P2
R84 = RT0603BRD0711KL: RES, 11.0 k, 0.1%, 0.1 W, 0603; Manufacturer: Yageo America; CompType: Resistor; Value: 11.0k; Res_ohm: 11000; Value_Code: 11k0; Tolerance_%: 0.1; Value2: 0.1W; VDC_V: 75; TempCo: 25 ppm/C; EIA_Code: E192; U/M: EA
R85 = RG1608P-1072-B-T5: RES, 10.7 k, 0.1%, 0.1 W, 0603; Manufacturer: Susumu Co Ltd; CompType: Resistor; Value: 10.7k; Res_ohm: 10700; Value_Code: 10k7; Tolerance_%: 0.1; Value2: 0.1W; VDC_V: 75; TempCo: 25 ppm/C; EIA_Code: E192; U/M: EA
U7 = TLC372QDR: as U5 on sheet TIDA-00905-E1_P2

## Sheet TIDA-00905-E1_Hardware.SchDoc: Hardware
size 431 x 279 mm; Date: Not shown in title block; ApprovedBy: Not shown in title block; CheckedBy: Not shown in title block; Author: Not shown in title block; CompanyName: Not shown in title block; DrawnBy: Sanjay Pithadia; Engineer: Not shown in title block; Organization: Not shown in title block; Address1: Not shown in title block; Address2: Not shown in title block; Address3: Not shown in title block; Address4: Not shown in title block; DocumentNumber: 1; Revision: Use project parameter SCH_Rev; SheetNumber: 6; SheetTotal: 6; PageSetup: Record=PageOptions¦CenterHorizontal=True¦CenterVertical=True¦PrintScale=1.00¦XCorrection=1.00¦YCorrection=1.00¦PrintKind=0¦BorderSize=5000000¦LeftOffset=0¦BottomOffset=0¦Orientation=2¦PaperLength=1000¦PaperWidth=1000¦Scale=100¦PaperSource=15¦PrintQuality=600¦MediaType=1¦DitherType=10¦PaperKind=Letter¦PrintScaleMode=1
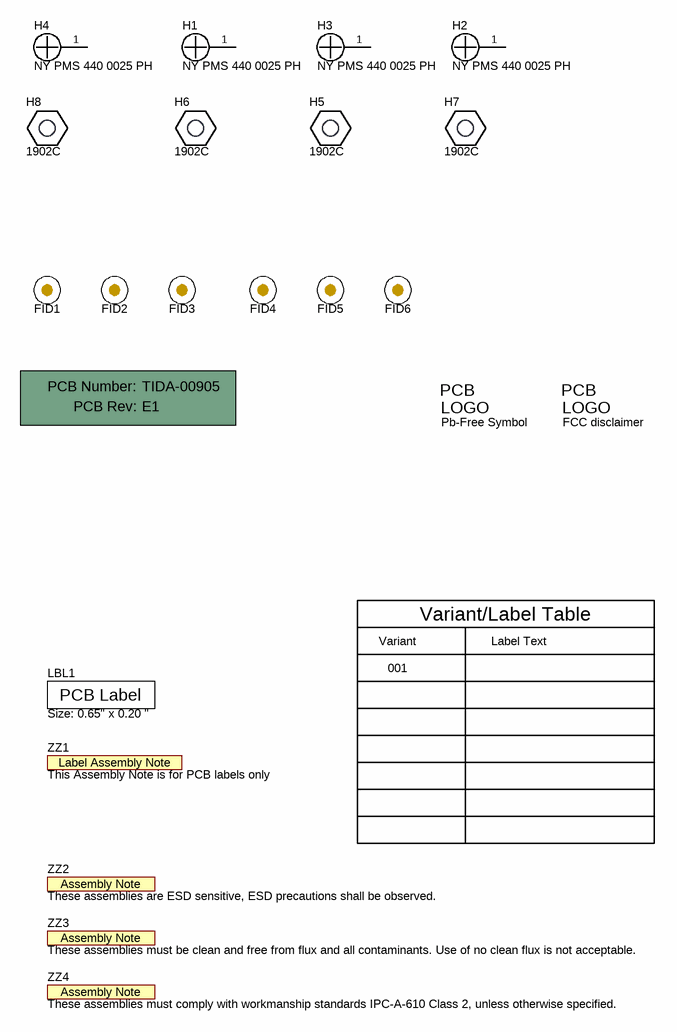
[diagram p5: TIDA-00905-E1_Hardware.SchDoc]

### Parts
!PCB1  Printed Circuit Board  (value not drawn)  (mechanical)
FID1  Fiducial  [Fiducial10-20]  (value not drawn)
FID2  Fiducial  [Fiducial10-20]  (value not drawn)
FID3  Fiducial  [Fiducial10-20]  (value not drawn)
FID4  Fiducial  [Fiducial10-20]  (value not drawn)
FID5  Fiducial  [Fiducial10-20]  (value not drawn)
FID6  Fiducial  [Fiducial10-20]  (value not drawn)
H1  NY PMS 440 0025 PH  [NY PMS 440 0025 PH]
H2  NY PMS 440 0025 PH  [NY PMS 440 0025 PH]
H3  NY PMS 440 0025 PH  [NY PMS 440 0025 PH]
H4  NY PMS 440 0025 PH  [NY PMS 440 0025 PH]
H5  1902C  [Keystone_1902C]
H6  1902C  [Keystone_1902C]
H7  1902C  [Keystone_1902C]
H8  1902C  [Keystone_1902C]
LBL1  Size: 0.65" x 0.20 "  [Label_650x200]
Logo1  Pb-Free Symbol  [Pb-Free_Overlay_Small]  (no BOM)
Logo3  FCC disclaimer  [FCC_disclaimer]  (no BOM)
ZZ1  This Assembly Note is for PCB labels only  [AssemblyNoteLabel]  (no BOM)
ZZ2  These assemblies are ESD sensitive, ESD precautions shall be observed.  [AssemblyNote]  (no BOM)
ZZ3  These assemblies must be clean and free from flux and all contaminants. Use of no clean flux is not acceptable.  [AssemblyNote]  (no BOM)
ZZ4  These assemblies must comply with workmanship standards IPC-A-610 Class 2, unless otherwise specified.  [AssemblyNote]  (no BOM)

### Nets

Not connected (* = marked no-connect by the designer): H1 1; H2 1; H3 1; H4 1

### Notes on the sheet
- Variant
- Variant/Label Table
- Label Text
- 001

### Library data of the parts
!PCB1 = PCB: Manufacturer: Any; PartNumber: TIDA-00905; SymbolCreator: a0412235
FID1-FID6 = Fiducial: Fiducial mark.  There is nothing to buy or mount.; SymbolCreator: codlsc
H1-H4 = NY PMS 440 0025 PH: Machine Screw, Round, #4-40 x 1/4, Nylon, Philips panhead; Manufacturer: B&F Fastener Supply; CompType: Hardware; SymbolCreator: codlsc; U/M: EA
H5-H8 = 1902C: Standoff, Hex, 0.5"L #4-40 Nylon; Manufacturer: Keystone; CompType: Hardware
LBL1 = THT-14-423-10: Thermal Transfer Printable Labels, 0.650" W x 0.200" H - 10,000 per roll; Manufacturer: Brady; SymbolCreator: a0412235; CompType: Label
Logo1 = Pb-Free: SymbolCreator: a0412235
Logo3 = FCC_disclaimer: SymbolCreator: codlsc
ZZ1 = AssemblyNoteLabel: SymbolCreator: a0412235
ZZ2-ZZ4 = AssemblyNote: SymbolCreator: codlsc

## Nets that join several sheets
GND: TIDA-00905-E1_P1 (10 pins), TIDA-00905-E1_P2 (48 pins), TIDA-00905-E1_P3 (29 pins), TIDA-00905-E1_P4 (16 pins)
VDD: TIDA-00905-E1_P1 (10 pins), TIDA-00905-E1_P2 (34 pins), TIDA-00905-E1_P3 (20 pins), TIDA-00905-E1_P4 (8 pins)
DEMAG: TIDA-00905-E1_P2 (U2.18 U3.18), TIDA-00905-E1_P3 (5 pins)
ER-U: TIDA-00905-E1_P2 (D12.1 U3.19), TIDA-00905-E1_P4 (J13.9)
ER-V: TIDA-00905-E1_P2 (D4.1 U2.19), TIDA-00905-E1_P4 (J13.5)
ER-W: TIDA-00905-E1_P3 (D6.1 U1.19), TIDA-00905-E1_P4 (J13.1)
GND_FAULT: TIDA-00905-E1_P3 (J10.2), TIDA-00905-E1_P4 (D17.1 R78.2 R80.2)
GSEL0: TIDA-00905-E1_P2 (R20.1 R33.1 R90.1 U3.1), TIDA-00905-E1_P3 (R18.1 R31.1 U1.1)
GSEL1: TIDA-00905-E1_P2 (R8.1 R11.1 R91.1 U3.20), TIDA-00905-E1_P3 (R6.1 R9.1 U1.20)
OC_FAULT: TIDA-00905-E1_P2 (D14.1 D15.1 R52.2 R53.2), TIDA-00905-E1_P3 (D13.1 J10.1 R51.2)
OR-U: TIDA-00905-E1_P2 (D11.1 U3.15), TIDA-00905-E1_P4 (J13.11)
OR-V: TIDA-00905-E1_P2 (D5.1 U2.15), TIDA-00905-E1_P4 (J13.7)
OR-W: TIDA-00905-E1_P3 (D7.1 U1.15), TIDA-00905-E1_P4 (J13.3)
REFOUT-U: TIDA-00905-E1_P2 (C16.1 R47.2), TIDA-00905-E1_P3 (J8.1 R87.1), TIDA-00905-E1_P4 (J13.18)
REFOUT-V: TIDA-00905-E1_P2 (C15.1 R46.2), TIDA-00905-E1_P3 (J9.1 R86.1 R87.2), TIDA-00905-E1_P4 (J13.10)
REFOUT-W: TIDA-00905-E1_P3 (C12.1 J7.1 R45.2 R86.2), TIDA-00905-E1_P4 (J13.2)
RSEL0: TIDA-00905-E1_P2 (R56.1 R62.1 R88.1 U3.3), TIDA-00905-E1_P3 (R54.1 R60.1 U1.3)
RSEL1: TIDA-00905-E1_P2 (R38.1 R50.1 R89.1 U3.2), TIDA-00905-E1_P3 (R36.1 R48.1 U1.2)
VO-U: TIDA-00905-E1_P2 (R42.1 R44.1 U3.6), TIDA-00905-E1_P4 (R81.1)
VO-V: TIDA-00905-E1_P2 (R41.1 R43.1 U2.6), TIDA-00905-E1_P4 (R79.1)
VO-W: TIDA-00905-E1_P3 (R39.1 R40.1 U1.6), TIDA-00905-E1_P4 (R77.1)
VOUT-U: TIDA-00905-E1_P2 (C19.1 J6.1 R44.2), TIDA-00905-E1_P4 (J13.19)
VOUT-V: TIDA-00905-E1_P2 (C18.1 J5.1 R43.2), TIDA-00905-E1_P4 (J13.14)
VOUT-W: TIDA-00905-E1_P3 (C17.1 J4.1 R40.2), TIDA-00905-E1_P4 (J13.6)

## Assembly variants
001: not fitted C1 C12 C15 C16 C17 C18 C19 R2 R6 R8 R9 R10 R11 R18 R19 R20 R26 R30 R31 R33 R36 R38 R48 R49 R50 R54 R56 R60 R61 R62 R75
